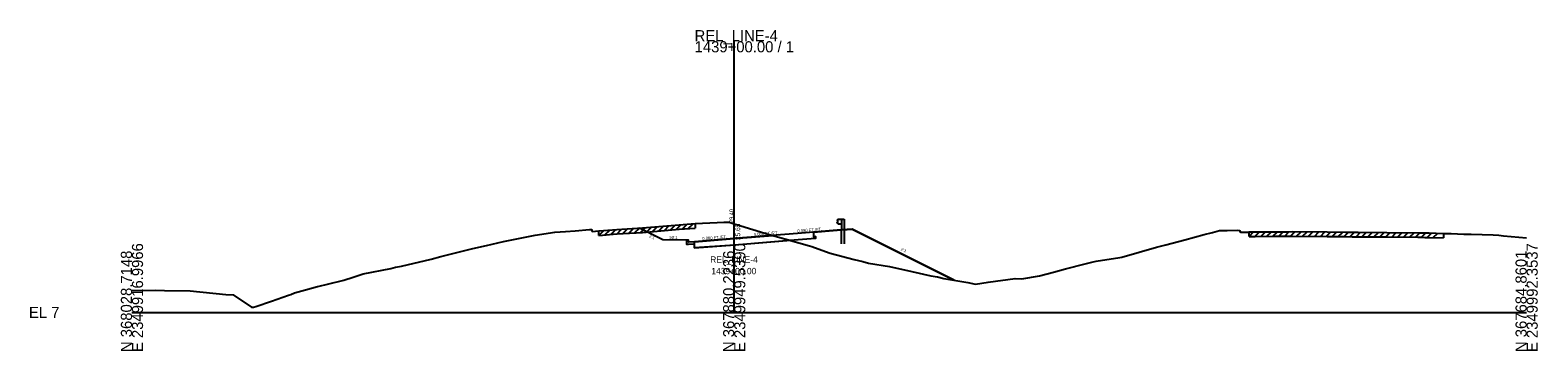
# Model space of a CAD drawing. Extents: x -26 to 2350146, y -10 to 368200.
# Drawn here: x 1974.3 to 2354.9, y 990.3 to 1071.3 of the extents above; entities that cross this region are included whole.
import ezdxf

# ---------------------------------------------------------------- set-up
doc = ezdxf.new("R2010")
doc.units = 0
for name, color, linetype in [('RD_GPK_XS_Cell', 7, 'Continuous'), ('RD_XS_Base', 7, 'Continuous'), ('RD_XS_CurbBase', 7, 'Continuous'), ('RD_XS_CurbFront', 7, 'Continuous'), ('RD_XS_CurbTop', 7, 'Continuous'), ('RD_XS_EarthShd', 7, 'Continuous'), ('RD_XS_EwShp', 7, 'Continuous'), ('RD_XS_ExGround', 7, 'Continuous'), ('RD_XS_ExPaveRet', 7, 'Continuous'), ('RD_XS_GR', 7, 'Continuous'), ('RD_XS_Pave', 7, 'Continuous'), ('RD_XS_PaveShd', 7, 'Continuous'), ('RD_XS_TieSlope', 7, 'Continuous'), ('RD_XS_TX_Elev_EX', 7, 'Continuous'), ('RD_XS_TX_Elev_PR', 7, 'Continuous'), ('RD_XS_TX_Slope', 7, 'Continuous'), ('RD_XS_TX_Station', 7, 'Continuous'), ('RD_XS_TX_TOC', 7, 'Continuous')]:
    doc.layers.add(name, color=color, linetype=linetype)

msp = doc.modelspace()

# ---------------------------------------------------------------- linework, layer by layer
at = {"layer": 'RD_GPK_XS_Cell'}
for p, q in [((2152.02, 1000), (2152.02, 1068.46)), ((2000, 1000), (2152.02, 1000)), ((2152.02, 1000), (2352.02, 1000))]:
    msp.add_line(p, q, dxfattribs=at)
at = {"layer": 'RD_XS_Base'}
for p, q in [((2172.02, 1020.25), (2172.02, 1019.11)), ((2152.15, 1017.02), (2142.02, 1016.21)), ((2168.15, 1018.3), (2152.15, 1017.02)), ((2172.52, 1018.65), (2168.15, 1018.3)), ((2172.52, 1019.15), (2172.52, 1018.65))]:
    msp.add_line(p, q, dxfattribs=at)
at = {"layer": 'RD_XS_CurbBase'}
for p, q in [((2140.01, 1018.25), (2140.01, 1017.25)), ((2140.01, 1017.25), (2140.51, 1017.25)), ((2140.51, 1017.25), (2142.01, 1017.33)), ((2142.02, 1016.27), (2142.01, 1017.33)), ((2172.52, 1019.15), (2172.02, 1019.11))]:
    msp.add_line(p, q, dxfattribs=at)
at = {"layer": 'RD_XS_CurbFront'}
msp.add_line((2142.01, 1017.33), (2142.01, 1017.83), dxfattribs=at)
at = {"layer": 'RD_XS_CurbTop'}
for p, q in [((2140.51, 1018.25), (2140.01, 1018.25)), ((2140.6, 1017.75), (2140.51, 1018.25)), ((2142.01, 1017.83), (2140.6, 1017.75)), ((2142.02, 1017.85), (2142.01, 1017.83))]:
    msp.add_line(p, q, dxfattribs=at)
at = {"layer": 'RD_XS_EarthShd'}
for p, q in [((2172.02, 1020.25), (2178.02, 1020.73)), ((2140.01, 1018.25), (2134.01, 1018.37))]:
    msp.add_line(p, q, dxfattribs=at)
at = {"layer": 'RD_XS_EwShp'}
for points in [[(2128.12, 1021.31), (2128.85, 1021.36), (2138.16, 1022.13), (2142.17, 1022.46), (2147.71, 1022.68), (2149.43, 1022.77), (2150.74, 1022.82), (2152.02, 1022.4), (2152.55, 1022.23), (2160.8, 1019.69), (2161.75, 1019.43), (2152.02, 1018.65), (2142.01, 1017.83), (2140.6, 1017.75), (2140.51, 1018.25), (2140.01, 1018.25), (2134.01, 1018.37)], [(2166.27, 1018.15), (2171.01, 1016.8), (2171.6, 1016.61), (2172.32, 1016.36), (2176.27, 1014.97), (2182.31, 1013.34), (2184.52, 1012.87), (2185.94, 1012.41), (2191.17, 1011.58), (2196.81, 1010.35), (2201.64, 1009.24), (2203.33, 1009.01), (2204.93, 1008.61), (2207.49, 1008.17), (2181.77, 1021.03), (2178.02, 1020.73), (2172.02, 1020.25), (2172.02, 1019.11), (2172.52, 1019.15), (2172.52, 1018.65), (2168.15, 1018.3)], [(2140.01, 1018.25), (2140.01, 1017.25), (2140.51, 1017.25), (2142.01, 1017.33), (2142.01, 1017.83), (2140.6, 1017.75), (2140.51, 1018.25)], [(2166.27, 1018.15), (2152.15, 1017.02), (2142.02, 1016.27), (2142.01, 1017.33), (2142.01, 1017.83), (2152.02, 1018.65), (2161.75, 1019.43), (2162.33, 1019.27)]]:
    msp.add_lwpolyline(points, close=True, dxfattribs=at)
at = {"layer": 'RD_XS_ExGround'}
msp.add_lwpolyline([(2000, 1005.53), (2005.88, 1005.59), (2008.25, 1005.53), (2014.73, 1005.45), (2023.69, 1004.56), (2025.53, 1004.44), (2030.19, 1001.32), (2030.66, 1001.31), (2031.27, 1001.49), (2035.19, 1002.86), (2039.55, 1004.38), (2040.07, 1004.56), (2041.07, 1004.92), (2043.77, 1005.67), (2046.82, 1006.53), (2047.27, 1006.6), (2049.35, 1007.1), (2053.52, 1008.17), (2055.85, 1008.89), (2058.36, 1009.77), (2065.36, 1011.09), (2066.54, 1011.41), (2068, 1011.68), (2075.51, 1013.47), (2077.96, 1014.11), (2086.03, 1016.18), (2089.46, 1016.94), (2093.77, 1017.92), (2099.63, 1019.09), (2101.78, 1019.52), (2106.71, 1020.23), (2109.41, 1020.42), (2111.87, 1020.61), (2115.46, 1020.95), (2116.02, 1020.96), (2116.2, 1020.46), (2117.88, 1020.58), (2122.42, 1020.95), (2128.85, 1021.36), (2138.16, 1022.13), (2142.17, 1022.46), (2147.71, 1022.68), (2149.43, 1022.77), (2150.74, 1022.82), (2152.02, 1022.4), (2152.55, 1022.23), (2160.8, 1019.69), (2162.33, 1019.27), (2171.01, 1016.8), (2171.6, 1016.61), (2172.32, 1016.36), (2176.27, 1014.97), (2182.31, 1013.34), (2184.52, 1012.87), (2185.94, 1012.41), (2191.17, 1011.58), (2196.81, 1010.35), (2201.64, 1009.24), (2203.33, 1009.01), (2204.93, 1008.61), (2210.94, 1007.58), (2212.94, 1007.14), (2216.09, 1007.62), (2222.92, 1008.59), (2224.65, 1008.48), (2229.06, 1009.27), (2232.59, 1010.19), (2235.62, 1010.97), (2240.57, 1012.24), (2242.65, 1012.75), (2243.41, 1012.97), (2249.34, 1013.85), (2249.81, 1013.97), (2258.62, 1016.5), (2260.92, 1017.07), (2265.73, 1018.31), (2270.64, 1019.67), (2272.7, 1020.21), (2274.52, 1020.69), (2276.43, 1020.71), (2278.93, 1020.75), (2279.58, 1020.69), (2279.81, 1020.28), (2281.32, 1020.28), (2281.75, 1020.29), (2281.96, 1020.33), (2283.48, 1020.35), (2288.49, 1020.37), (2291.88, 1020.39), (2292.92, 1020.4), (2301.68, 1020.33), (2306.3, 1020.29), (2308, 1020.27), (2309.54, 1020.26), (2316.73, 1020.2), (2324.59, 1020.12), (2325.51, 1020.11), (2326.36, 1020.11), (2327.41, 1020.08), (2331.07, 1019.97), (2332.95, 1019.93), (2336.21, 1019.73), (2338.01, 1019.78), (2343.61, 1019.61), (2345.04, 1019.48), (2346.2, 1019.36), (2352.02, 1018.81)], dxfattribs=at)
at = {"layer": 'RD_XS_ExPaveRet'}
for p, q in [((2117.88, 1019.44), (2119.13, 1020.68)), ((2117.88, 1019.44), (2117.88, 1020.58)), ((2119.38, 1019.56), (2120.63, 1020.8)), ((2120.88, 1019.68), (2122.13, 1020.93)), ((2122.38, 1019.8), (2123.6, 1021.03)), ((2122.42, 1019.81), (2128.85, 1020.22)), ((2123.88, 1019.9), (2125.1, 1021.12)), ((2125.38, 1020), (2126.6, 1021.22)), ((2126.88, 1020.09), (2128.1, 1021.31)), ((2128.38, 1020.19), (2129.62, 1021.42)), ((2128.85, 1020.22), (2138.16, 1020.99)), ((2129.88, 1020.3), (2131.13, 1021.55)), ((2131.38, 1020.43), (2132.63, 1021.67)), ((2132.88, 1020.55), (2134.13, 1021.8)), ((2134.38, 1020.67), (2135.63, 1021.92)), ((2135.88, 1020.8), (2137.13, 1022.04)), ((2137.38, 1020.92), (2138.63, 1022.17)), ((2138.16, 1020.99), (2142.17, 1021.31)), ((2138.88, 1021.04), (2140.13, 1022.29)), ((2140.38, 1021.17), (2141.63, 1022.41)), ((2142.17, 1022.46), (2142.17, 1021.31)), ((2281.96, 1019.19), (2283.12, 1020.34)), ((2281.96, 1019.19), (2281.96, 1020.33)), ((2283.46, 1019.2), (2284.61, 1020.35)), ((2284.96, 1019.21), (2286.11, 1020.36)), ((2286.46, 1019.22), (2287.61, 1020.37)), ((2287.96, 1019.23), (2289.11, 1020.38)), ((2289.46, 1019.24), (2290.61, 1020.39)), ((2290.96, 1019.25), (2292.12, 1020.4)), ((2292.46, 1019.26), (2293.61, 1020.4)), ((2293.96, 1019.25), (2295.1, 1020.38)), ((2295.46, 1019.24), (2296.6, 1020.37)), ((2296.96, 1019.22), (2298.1, 1020.36)), ((2298.46, 1019.21), (2299.6, 1020.35)), ((2299.96, 1019.2), (2301.1, 1020.33)), ((2301.46, 1019.19), (2302.6, 1020.32)), ((2302.96, 1019.17), (2304.1, 1020.31)), ((2304.46, 1019.16), (2305.6, 1020.3)), ((2305.96, 1019.15), (2307.1, 1020.28)), ((2307.46, 1019.14), (2308.6, 1020.27)), ((2308.96, 1019.12), (2310.1, 1020.26)), ((2310.46, 1019.11), (2311.6, 1020.24)), ((2311.96, 1019.1), (2313.1, 1020.23)), ((2313.46, 1019.08), (2314.6, 1020.22)), ((2314.96, 1019.07), (2316.1, 1020.2)), ((2316.46, 1019.06), (2317.6, 1020.19)), ((2317.96, 1019.04), (2319.1, 1020.17)), ((2319.46, 1019.03), (2320.6, 1020.16)), ((2320.96, 1019.01), (2322.1, 1020.15)), ((2322.46, 1019), (2323.6, 1020.13)), ((2323.96, 1018.98), (2325.1, 1020.12)), ((2325.46, 1018.97), (2326.59, 1020.1)), ((2326.96, 1018.95), (2328.08, 1020.06)), ((2328.46, 1018.9), (2329.57, 1020.01)), ((2331.07, 1019.97), (2331.07, 1018.82)), ((2117.88, 1019.44), (2122.42, 1019.81)), ((2281.96, 1019.19), (2283.48, 1019.2)), ((2283.48, 1019.2), (2288.49, 1019.23)), ((2288.49, 1019.23), (2291.88, 1019.25)), ((2291.88, 1019.25), (2292.92, 1019.26)), ((2292.92, 1019.26), (2301.68, 1019.18)), ((2301.68, 1019.18), (2306.3, 1019.15)), ((2306.3, 1019.15), (2308, 1019.13)), ((2308, 1019.13), (2309.54, 1019.12)), ((2309.54, 1019.12), (2316.73, 1019.05)), ((2316.73, 1019.05), (2324.59, 1018.98)), ((2324.59, 1018.98), (2325.51, 1018.97)), ((2325.51, 1018.97), (2326.36, 1018.96)), ((2326.36, 1018.96), (2327.41, 1018.93)), ((2327.41, 1018.93), (2331.07, 1018.82))]:
    msp.add_line(p, q, dxfattribs=at)
at = {"layer": 'RD_XS_GR'}
for p, q in [((2178.18, 1023.48), (2178.01, 1023.28)), ((2178.01, 1023.28), (2178.01, 1023.23)), ((2178.01, 1023.23), (2178.18, 1023.03)), ((2178.01, 1022.71), (2178.18, 1022.91)), ((2178.01, 1022.66), (2178.01, 1022.71)), ((2178.18, 1022.46), (2178.01, 1022.66)), ((2178.18, 1023.55), (2179.09, 1023.55)), ((2178.18, 1022.38), (2178.18, 1023.55)), ((2178.18, 1022.38), (2179.09, 1022.38)), ((2179.09, 1023.55), (2179.76, 1023.55)), ((2179.09, 1023.55), (2179.09, 1020.81)), ((2179.09, 1017.34), (2179.09, 1020.81)), ((2179.76, 1023.55), (2179.76, 1020.75)), ((2179.76, 1020.75), (2179.76, 1017.34))]:
    msp.add_line(p, q, dxfattribs=at)
at = {"layer": 'RD_XS_Pave'}
for p, q in [((2168.02, 1019.93), (2152.02, 1018.65)), ((2152.02, 1018.65), (2142.02, 1017.85))]:
    msp.add_line(p, q, dxfattribs=at)
at = {"layer": 'RD_XS_PaveShd'}
msp.add_line((2172.02, 1020.25), (2168.02, 1019.93), dxfattribs=at)
at = {"layer": 'RD_XS_TieSlope'}
for p, q in [((2134.01, 1018.37), (2128.12, 1021.31)), ((2178.02, 1020.73), (2181.77, 1021.03)), ((2181.77, 1021.03), (2207.49, 1008.17))]:
    msp.add_line(p, q, dxfattribs=at)

# ---------------------------------------------------------------- texts
at = {"layer": 'RD_GPK_XS_Cell'}
for s, p in [('REL_LINE-4', (2142.02, 1068.46)), ('1439+00.00 / 1', (2142.02, 1065.66)), ('EL 7', (1974, 998.6))]:
    msp.add_text(s, height=2.8, dxfattribs=at).set_placement(p)
for s, p in [('E 2349916.9966', (2002.8, 990)), ('E 2349949.5390', (2154.82, 990)), ('E 2349992.3537', (2354.82, 990)), ('N 368028.7148', (2000, 990)), ('N 367880.2236', (2152.02, 990)), ('N 367684.8601', (2352.02, 990))]:
    msp.add_text(s, height=2.8, rotation=90, dxfattribs=at).set_placement(p)
at = {"layer": 'RD_XS_TX_Elev_EX'}
msp.add_text('29.40', height=1, rotation=90, dxfattribs=at).set_placement((2151.82, 1022.62))
at = {"layer": 'RD_XS_TX_Elev_PR'}
msp.add_text(' 25.65', height=1.2, rotation=90, dxfattribs=at).set_placement((2153.53, 1017.82))
at = {"layer": 'RD_XS_TX_Slope'}
for s, rotation, p in [('0.080 FT./FT.', 4.5739, (2156.98, 1019.3)), ('0.080 FT./FT.', 4.5739, (2167.98, 1020.18)), ('2:1', 333.4349, (2130.45, 1019.02)), ('50:1', 358.8542, (2135.67, 1018.58)), ('0.080 FT./FT.', 4.5739, (2143.98, 1018.26)), ('2:1', 333.4349, (2193.98, 1015.73))]:
    msp.add_text(s, height=0.75, rotation=rotation, dxfattribs=at).set_placement(p)
at = {"layer": 'RD_XS_TX_Station'}
for s, p in [('REL_LINE-4', (2145.95, 1012.55)), ('1439+00.00', (2146.24, 1009.65))]:
    msp.add_text(s, height=1.6, dxfattribs=at).set_placement(p)
at = {"layer": 'RD_XS_TX_TOC'}
msp.add_text('TOCLT', height=0.05, dxfattribs=at).set_placement((2140.56, 1018.2))

doc.saveas('drawing.dxf')
